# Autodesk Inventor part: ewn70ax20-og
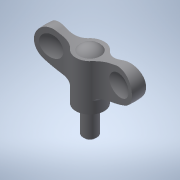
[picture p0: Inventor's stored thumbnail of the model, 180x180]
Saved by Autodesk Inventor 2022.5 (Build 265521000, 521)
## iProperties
Created: 2016-12
Part Number: ewn70ax20-og
Material: 一般
Document SubType Name: Modeling
Designer: imaocorp
Density: 1 g/cm^3
Appearance: 既定
Author: imaocorp
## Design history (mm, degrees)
node "ewn70ax20-og.x_t1"
node "ewn70ax20-og"
node "Base1"
